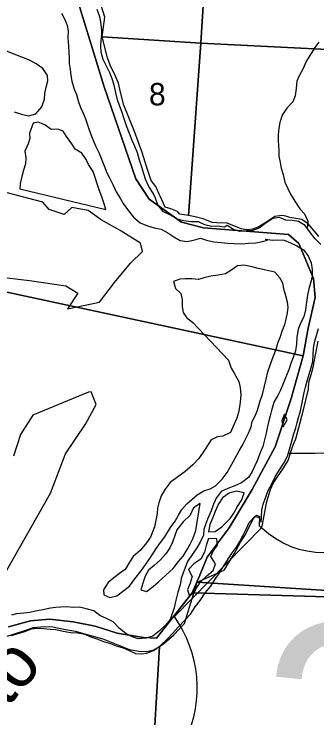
# Model space of a CAD drawing. Extents: x 114604 to 551442, y 316898 to 567001.
# Drawn here: x 203011 to 206000, y 360166 to 367116 of the extents above; entities that cross this region are included whole.
import ezdxf

# ---------------------------------------------------------------- set-up
doc = ezdxf.new("R2010")
doc.units = 0
for name, color, linetype in [('DV_X_County_Line', 7, 'Continuous'), ('GE_P_Alignment_500_Cardinal_Points', 7, 'Continuous'), ('GE_P_Alignment_500_Distances', 7, 'Continuous'), ('MT_X_Edge_Line', 7, 'Continuous'), ('PM_P_Cells', 7, 'Continuous'), ('PV_X_Curb', 7, 'Continuous'), ('RD_P_GR_Rt', 7, 'Continuous'), ('SN_P_Signs', 7, 'Continuous')]:
    doc.layers.add(name, color=color, linetype=linetype)

msp = doc.modelspace()

# ---------------------------------------------------------------- linework, layer by layer
at = {"layer": 'DV_X_County_Line'}
for points in [[(203480.5, 367126.5), (203514.6, 367056.4), (203534.7, 367002.3), (203544.7, 366952.3), (203542.8, 366882.1), (203546.9, 366802), (203551, 366737.9), (203555.1, 366679.8), (203555.1, 366627.7), (203563.2, 366567.6), (203571.3, 366509.5), (203581.4, 366453.4), (203605.5, 366373.3), (203625.5, 366321.2), (203647.6, 366251.1), (203667.7, 366195), (203693.8, 366136.9), (203715.9, 366080.9), (203740, 366012.8), (203754, 365962.7), (203782.1, 365894.6), (203816.2, 365816.5), (203846.3, 365750.4), (203872.4, 365682.3), (203900.5, 365616.2), (203926.6, 365548.1), (203952.6, 365498.1), (203984.7, 365432), (204018.8, 365361.9), (204058.9, 365297.9), (204089, 365245.8), (204141.1, 365173.7), (204189.2, 365111.7), (204255.3, 365055.7), (204327.3, 365025.7), (204395.3, 365005.7), (204463.4, 364991.8), (204529.4, 364955.8), (204589.5, 364915.8), (204651.5, 364879.9), (204715.6, 364871.9), (204781.6, 364884), (204849.5, 364902.1), (204911.6, 364884.2), (204981.6, 364868.3), (205053.6, 364860.3), (205119.6, 364852.4), (205183.7, 364850.5), (205255.7, 364848.6)], [(204270.6, 365604.7), (204250.5, 365674.8), (204228.4, 365744.9), (204200.3, 365817), (204178.2, 365869.1), (204150.1, 365937.2), (204122, 366013.3), (204095.9, 366091.4), (204077.8, 366143.5), (204051.8, 366213.5), (204031.7, 366269.6), (204015.6, 366337.7), (204001.5, 366401.8), (203983.4, 366465.9), (203959.3, 366530), (203923.2, 366602.1), (203889.1, 366668.2), (203871.1, 366740.3), (203867, 366804.4), (203870.9, 366854.5), (203876.8, 366904.6), (203876.8, 366956.7), (203868.7, 367038.8), (203856.6, 367088.9), (203830.5, 367161)], [(205089.4, 365010.7), (205017.4, 365020.6), (204963.4, 365018.5), (204895.4, 365036.5), (204831.3, 365064.4), (204759.3, 365064.3), (204687.3, 365074.3), (204619.3, 365092.2), (204555.2, 365130.2), (204485.2, 365164.2), (204431.1, 365232.2), (204407, 365298.3), (204382.9, 365348.4), (204340.8, 365412.4), (204308.7, 365484.5), (204290.6, 365538.6), (204270.6, 365604.7)], [(206039.8, 364841.6), (205981.7, 364897.6), (205925.6, 364969.7), (205883.6, 365029.7), (205819.5, 365067.7), (205757.5, 365077.7), (205693.5, 365081.6), (205631.4, 365107.6), (205565.4, 365097.4), (205499.5, 365053.3), (205431.5, 365003.1), (205363.5, 364979), (205311.5, 364974.9), (205239.5, 364968.8), (205175.5, 364988.7), (205115.4, 365028.7), (205089.4, 365010.7)], [(205511.7, 364883), (205493.7, 364895), (205561.7, 364885), (205611.7, 364887.1), (205677.7, 364885.2), (205739.7, 364857.2), (205801.8, 364827.3), (205867.9, 364787.3), (205913.9, 364729.2), (205944, 364661.1), (205952.1, 364595), (205954.2, 364522.9), (205940.3, 364472.8), (205920.4, 364404.6), (205906.4, 364340.5), (205896.5, 364272.3), (205888.6, 364196.2), (205870.7, 364126), (205838.8, 364063.9), (205814.8, 364001.7), (205802.9, 363925.6), (205799, 363857.5), (205789.1, 363791.3), (205767.2, 363725.2), (205743.3, 363665), (205723.3, 363602.9), (205697.4, 363540.7), (205671.5, 363474.6), (205639.6, 363402.4), (205613.6, 363350.3), (205579.7, 363290.1), (205555.8, 363215.9), (205537.9, 363149.8), (205525.9, 363099.7), (205510, 363031.5), (205500.1, 362977.4), (205482.2, 362913.3), (205466.2, 362845.1), (205444.3, 362793), (205410.4, 362704.8), (205362.5, 362600.6), (205324.6, 362538.4), (205256.7, 362488.2), (205188.7, 362458.1), (205120.7, 362429.9), (205054.7, 362401.8), (205006.8, 362335.6), (204978.9, 362275.4), (204955, 362209.3), (204921.1, 362129.1), (204899.1, 362075), (204885.2, 362024.9), (204879.2, 361970.8), (204847.3, 361902.6), (204813.4, 361846.4), (204771.5, 361782.3), (204723.6, 361712.1), (204699.6, 361651.9), (204679.7, 361597.8), (204661.8, 361541.7), (204649.8, 361481.5), (204625.9, 361407.4), (204608, 361327.2), (204590.1, 361253), (204550.3, 361136.8), (204510.3, 361084.6), (204446.4, 361024.4), (204380.4, 360974.3), (204312.4, 360954.1), (204236.4, 360948), (204176.4, 360966), (204114.4, 360998), (204050.3, 361048), (203988.2, 361116), (203924.1, 361148), (203858.1, 361176), (203798, 361222), (203724, 361241.9), (203658, 361259.8), (203595.9, 361257.8), (203527.9, 361263.7), (203471.9, 361259.6), (203421.9, 361257.5), (203369.9, 361249.5), (203293.9, 361233.3), (203223.9, 361221.2), (203167.9, 361207.1), (203105.9, 361199), (203033.9, 361192.9), (202983.9, 361180.8)], [(205255.7, 364848.6), (205323.7, 364852.7), (205395.7, 364858.8), (205461.7, 364870.9), (205511.7, 364883)], [(203184.1, 361044.8), (203236.1, 361050.9), (203300.2, 361049), (203368.2, 361043.1), (203422.2, 361039.1), (203496.2, 361023.2), (203568.2, 361009.3), (203640.3, 361005.4), (203708.3, 360991.4), (203760.3, 360971.4), (203826.4, 360945.5), (203894.4, 360921.5), (203962.4, 360901.6), (204018.5, 360877.6), (204088.5, 360857.7), (204140.6, 360833.7), (204208.6, 360801.7), (204272.6, 360799.8), (204322.6, 360805.9), (204386.6, 360832), (204454.6, 360876.2), (204522.5, 360944.4), (204578.4, 361002.6), (204630.4, 361062.8), (204698.3, 361133), (204752.2, 361189.1), (204800.1, 361261.3), (204848.1, 361325.5), (204896, 361399.7), (204951.9, 361465.9), (204995.8, 361536.1), (205031.8, 361590.3), (205065.7, 361642.4), (205111.6, 361712.6), (205157.5, 361784.8), (205207.5, 361853), (205239.4, 361907.1), (205273.3, 361969.3), (205305.2, 362035.4), (205331.2, 362095.6), (205389.1, 362155.8), (205426.3, 362146.8), (205449.2, 362099.7), (205453.1, 362151.8), (205457, 362220), (205471, 362276.1), (205500.9, 362354.3), (205514.8, 362404.4), (205554.7, 362476.6), (205588.6, 362546.7), (205632.6, 362616.9), (205674.5, 362683.1), (205710.4, 362751.3), (205726.3, 362805.4), (205746.3, 362875.6), (205770.2, 362961.8), (205792.1, 363031.9), (205806, 363082), (205819.9, 363132.1), (205835.9, 363186.3), (205851.8, 363260.4), (205865.7, 363328.6), (205873.6, 363380.7), (205887.6, 363430.8), (205901.5, 363482.9), (205925.4, 363561.1), (205943.3, 363625.2), (205959.3, 363685.3), (205963.2, 363755.5), (205967.1, 363817.6), (205979, 363887.7), (205995, 363941.9), (206014.9, 364010)], [(205681.9, 363164), (205654, 363099.9), (205668, 363041.8)], [(205668, 363041.8), (205705.9, 363110), (205681.9, 363164)], [(205282.8, 362390.1), (205202.8, 362404), (205132.8, 362385.9), (205066.8, 362339.7), (205024.9, 362273.5), (204995, 362205.3), (204973.1, 362145.2), (204943.1, 362077), (204929.2, 362004.9), (204995.2, 362007), (205063.2, 362053.2)], [(205063.2, 362053.2), (205145.1, 362135.4), (205179, 362187.6), (205214.9, 362253.7), (205258.9, 362319.9), (205282.8, 362390.1)], [(204929.3, 361936.8), (204907.4, 361868.6), (204889.5, 361802.5), (204855.5, 361734.3), (204785.6, 361686.1), (204733.7, 361629.9), (204767.7, 361563.9), (204749.8, 361495.7), (204723.9, 361435.6), (204742, 361365.5), (204795.9, 361413.6)], [(204795.9, 361413.6), (204803.9, 361435.7), (204851.8, 361509.9), (204913.8, 361568.1), (204977.7, 361622.2), (204999.6, 361686.4), (204951.5, 361758.5), (204977.5, 361812.6), (205019.4, 361870.8), (205013.3, 361932.9), (204929.3, 361936.8)], [(202984.2, 360980.4), (203116.2, 361020.7), (203184.1, 361044.8)]]:
    msp.add_lwpolyline(points, dxfattribs=at)
at = {"layer": 'GE_P_Alignment_500_Cardinal_Points'}
msp.add_line((205456.8, 362044.6), (204592.9, 361168.1), dxfattribs=at)
for centre, radius, start, end in [((206061.4, 362670.4), 870.2, 225.98646, 314.84047), ((203600.1, 360462.2), 1218.2, 334.96058, 35.41439)]:
    msp.add_arc(centre, radius, start, end, dxfattribs=at)
at = {"layer": 'GE_P_Alignment_500_Distances'}
for points in [[(203590.6, 367408.2), (203901.4, 366398.8), (204211.4, 365490.7), (204343, 365289.3), (204662.6, 365060.4), (204879.8, 365004.1), (205718.5, 364938), (205820.3, 364852), (205967.3, 364506.2), (205983.1, 364318.5), (205913.1, 364014.5), (205863.2, 363742), (199063.9, 365202.5)], [(207096.8, 361332.5), (204769.8, 361400.5), (204843.8, 361576.7), (204917.8, 361752.8), (205132.5, 362043.4), (205361, 362420.8), (205589.1, 362841.6), (205744.7, 363319.6), (205863.2, 363742), (205913.1, 364014.5), (205983.1, 364318.5), (205967.3, 364506.2), (205820.3, 364852), (205718.5, 364938), (204879.8, 365004.1), (204662.6, 365060.4), (204343, 365289.3), (204211.4, 365490.7), (203901.4, 366398.8), (203590.6, 367408.2)], [(199063.9, 365202.5), (205863.2, 363742), (205744.7, 363319.6), (205589.1, 362841.6), (205361, 362420.8), (205132.5, 362043.4), (204917.8, 361752.8), (204843.8, 361576.7), (204769.8, 361400.5), (204417.7, 360954.4), (204287.6, 360960.6), (204027.1, 361002.1), (203809.8, 361072.8), (203592.8, 361114.6), (203361.3, 361141.8), (203173.6, 361126), (202957.2, 361066.6)], [(202957.2, 361066.6), (203173.6, 361126), (203361.3, 361141.8), (203592.8, 361114.6), (203809.8, 361072.8), (204027.1, 361002.1), (204287.6, 360960.6), (204417.7, 360954.4), (204769.8, 361400.5), (207096.8, 361332.5), (208169.7, 361284.4), (208552.9, 361258.6), (209132.9, 361224.3), (209780.2, 361190.3), (210185.5, 361167.7), (211235.9, 361101.5), (211937.1, 361053.8), (213234, 360978.2), (213279.3, 360976.1), (214060.3, 360930.7), (215135.5, 360867.9), (217822.6, 360710.4), (220462.2, 360550.5), (222533.6, 360426.9)]]:
    msp.add_lwpolyline(points, dxfattribs=at)
at = {"layer": 'MT_X_Edge_Line'}
msp.add_line((203771.3, 363385.4), (203745.2, 363383.3), dxfattribs=at)
for points in [[(203161.7, 366660), (202175.7, 367047.1)], [(203010.4, 366149.8), (203084.3, 366127.3), (203154.2, 366112.9), (203226.4, 366132.5), (203284.8, 366200.2), (203311.3, 366276.2), (203315.7, 366332.3), (203328.1, 366394.4), (203342.5, 366458.4), (203340.8, 366510.6), (203293.2, 366579), (203227.5, 366623.5), (203161.7, 366660)], [(203916.7, 365186), (203901, 365242.2), (203877.4, 365312.5), (203851.9, 365380.8), (203793, 365561.6), (203745.4, 365630.1), (203721.7, 365680.3), (203678.1, 365742.7), (203612.3, 365783.2), (203580.6, 365833.5), (203527.1, 365908), (203495.4, 365958.4), (203441.5, 365980.7), (203375.4, 365975.2), (203313.7, 366023.7), (203249.8, 366048.1), (203199.7, 366038.4), (203163.1, 365940.4), (203164.8, 365886.3), (203150.4, 365834.3), (203117.9, 365762.3), (203125.5, 365698.1), (203125.1, 365636), (203102.7, 365574), (203086.3, 365512), (203071.9, 365443.9), (203067.5, 365391.8)], [(204257.6, 364852.4), (204057, 364980.1), (203870.6, 365085.8), (203742.2, 365175.5), (203581.9, 365207.1), (203505.9, 365136.7), (203357.6, 365186.3), (203295.4, 365260.3), (202551.8, 365454.4)], [(203067.5, 365391.8), (203916.7, 365186)], [(204279.8, 364772.3), (204257.6, 364852.4)], [(202885.9, 364519.2), (203162.4, 364484), (203523.1, 364433.1), (203641.4, 364359.3), (203537.5, 364206.6), (203853.9, 364271.8), (204003.8, 364466.7), (204159.8, 364657.7), (204279.8, 364772.3)], [(205127.8, 363697), (205153.3, 363620.7), (205185, 363570.4), (205228.5, 363487.9), (205244.1, 363427.7), (205249.7, 363355.5), (205243.2, 363283.4), (205228.6, 363195.3), (205208.2, 363127.3), (205179.7, 363059.3), (205147.2, 362983.3), (205071, 362947.7), (205018.9, 362942), (204956.7, 362912.4), (204896.1, 362818.6), (204833.4, 362728.8), (204775, 362665), (204696.5, 362595.3), (204626.2, 362545.6), (204551.8, 362490), (204503.3, 362424.2), (204462.9, 362360.3), (204438.4, 362288.3), (204428.1, 362236.2), (204421.8, 362186.1), (204396.9, 362054), (204356.3, 361950), (204317.9, 361896.2), (204255.4, 361820.4), (204187, 361760.7), (204148.6, 361702.8), (204106.1, 361630.9), (204051.8, 361591.2), (203995.5, 361549.4), (203939.2, 361503.7), (203894.7, 361431.8), (203898.4, 361381.7), (203956.2, 361355.2), (204024.4, 361372.8), (204094.8, 361422.5), (204151.1, 361466.2), (204201.5, 361538.1), (204266.1, 361617.9), (204312.5, 361683.7), (204359, 361751.6), (204411.5, 361833.4), (204447.9, 361885.3), (204500.3, 361953.1), (204555, 362045), (204601.4, 362108.8), (204633.8, 362168.8), (204668.1, 362224.7), (204716.5, 362280.5), (204766.8, 362322.3), (204817.1, 362368.1), (204883.4, 362409.7), (204947.6, 362427.4), (204997.8, 362459.1), (205064.3, 362524.8), (205114.7, 362588.7), (205143.1, 362642.6), (205193.7, 362732.5), (205234.1, 362802.4), (205264.5, 362858.3), (205290.8, 362910.3), (205325.3, 362976.2), (205349.7, 363040.2), (205362, 363094.2), (205394.4, 363154.1), (205414.8, 363206.1), (205441.4, 363296.2), (205461.8, 363358.2), (205480.2, 363430.2), (205500.8, 363512.3), (205517.3, 363584.3), (205541.8, 363660.3), (205568.2, 363732.3), (205596.7, 363808.3), (205619.2, 363876.3), (205641.5, 363932.3), (205657.9, 363984.3), (205682.3, 364052.3), (205696.7, 364104.4), (205711, 364164.4), (205717.4, 364220.5), (205709.7, 364270.6), (205694.1, 364332.9), (205678.5, 364389.1), (205662.9, 364457.3), (205635.2, 364511.6), (205583.6, 364568.1), (205497.6, 364588.7), (205421.7, 364603.2), (205361.8, 364619.6), (205279.8, 364636.2), (205217.8, 364628.5), (205149.4, 364582.9), (205099.2, 364551.1), (205027.1, 364537.5), (204953, 364528), (204884.9, 364512.4)], [(204884.9, 364512.4), (204830.7, 364496.7), (204764.7, 364503.1), (204700.7, 364501.5), (204646.6, 364497.8), (204584.5, 364474.2), (204604, 364405.9), (204655.7, 364355.5), (204669.3, 364293.3), (204670.9, 364225.1), (204680.6, 364170.9), (204712.3, 364120.6), (204771.5, 364073.2)], [(204884.9, 364512.4), (204830.7, 364496.7), (204764.7, 364503.1), (204700.7, 364501.5), (204646.6, 364497.8), (204584.5, 364474.2), (204604, 364405.9), (204655.7, 364355.5), (204669.3, 364293.3), (204670.9, 364225.1), (204680.6, 364170.9), (204712.3, 364120.6), (204778, 364068.1)], [(204771.5, 364073.2), (205127.8, 363697)], [(204771.5, 364073.2), (205127.8, 363697)], [(202940.9, 361624.5), (203370.3, 362385.7), (203517.9, 362773.1), (203715.7, 363066.4), (203821.6, 363259.2), (203771.3, 363385.4)], [(203745.2, 363383.3), (203196.7, 363157), (203072.9, 362964.1), (203005.1, 362749.4)], [(204846.6, 362281.7), (204782.3, 362240), (204749.8, 362168), (204679.4, 362102.3), (204618.8, 362022.5), (204598.5, 361966.5), (204574, 361900.6), (204549.7, 361846.6), (204509.3, 361786.7), (204452.8, 361722.9), (204392.5, 361671.2), (204338.1, 361623.4), (204305.8, 361565.5), (204281.3, 361495.5), (204260.9, 361429.5), (204318.8, 361415.1), (204383.2, 361464.8), (204437.5, 361508.5), (204507.9, 361574.2), (204580.4, 361641.9), (204634.9, 361709.7), (204679.2, 361763.6), (204719.6, 361827.5), (204750, 361881.4), (204776.4, 361935.4), (204804.9, 362015.3)], [(204804.9, 362015.3), (204846.6, 362281.7)]]:
    msp.add_lwpolyline(points, dxfattribs=at)
at = {"layer": 'PM_P_Cells'}
for points in [[(206019.3, 366839.5), (205981.2, 366785.4), (205929, 366707.3), (205898.9, 366653.3), (205860.7, 366573.1), (205824.6, 366507.1), (205802.5, 366455), (205794.3, 366380.9), (205784.2, 366308.8), (205764, 366248.7), (205701.9, 366188.6), (205655.8, 366118.5), (205635.6, 366046.4), (205623.5, 365988.3), (205619.3, 365924.2), (205619.2, 365868.1), (205621.1, 365816), (205623, 365765.9), (205624.9, 365713.8), (205636.7, 365651.7), (205648.6, 365593.6), (205668.4, 365531.5), (205684.2, 365457.3), (205714.1, 365395.2), (205739.9, 365339.1), (205781.8, 365268.9), (205831.6, 365192.7), (205877.4, 365142.6), (205911.3, 365070.4), (205904.2, 365000.2)], [(206201.9, 362766.1), (206046, 362780.3), (205984, 362778.3), (205920, 362778.4), (205717.8, 362776.3)]]:
    msp.add_lwpolyline(points, dxfattribs=at)
at = {"layer": 'SN_P_Signs'}
for points in [[(205184.9, 372126.8), (204854.1, 366827.9), (203880, 366893), (203907.8, 367087), (203793.4, 367445)], [(206020.1, 364918.9), (205994.1, 364952.9), (205914, 365044.8), (205849.9, 365086.8), (205731.9, 365108.6), (205693.9, 365120.6), (205653.9, 365126.6), (205583.9, 365118.5), (205523.9, 365074.4), (205426, 365014.3), (205364, 364992.3), (205308, 364986.2), (205252, 364994.2), (205113.9, 365050), (205011.9, 365053.9), (204965.9, 365057.9), (204877.9, 365095.8), (204797.8, 365113.7), (204731.8, 365127.6), (204854.1, 366827.9), (210120.7, 366565.7)], [(209779.5, 361186.3), (204817.4, 361505.3), (205083.3, 361625.6), (205183.1, 361785.8), (205245.1, 361899.8), (205295, 361975.9), (205362.8, 362118), (205386.8, 362152), (205404.8, 362168), (205432.8, 362156.1), (205430.9, 362062), (205444.9, 362050), (205460.9, 362058.1), (205504.7, 362304.1), (205541.6, 362421), (205572.5, 362488.2), (205674.4, 362638.3), (205716.3, 362706.4), (205754.2, 362822.4), (205768.1, 362870.4), (205792.1, 362922.5), (205865.8, 363196.6), (205915.6, 363412.7), (205921.5, 363482.7), (205945.5, 363566.7), (205963.4, 363630.7), (205989.3, 363768.8), (206013.2, 363886.8)], [(202921.7, 360965.4), (203117.7, 361027.6), (203203.7, 361057.7), (203309.7, 361067.8), (203393.7, 361065.9), (203518, 361040.4), (203617.8, 361024.1), (203719.8, 360994.2), (203885.9, 360948.4), (204050, 360882.5), (204148, 360840.6), (204244, 360824.7), (204322, 360820.8), (204390, 360836.9), (204446, 360870.9), (204166.6, 356134.1), (200846.1, 356348.9)]]:
    msp.add_lwpolyline(points, dxfattribs=at)
for points in [[(210406.1, 371835), (210120.7, 366565.7), (204854.1, 366827.9), (205184.9, 372126.8)], [(204854.1, 366827.9), (204731.8, 365127.6), (204647.8, 365141.6), (204625.7, 365167.6), (204557.7, 365193.5), (204503.7, 365209.4), (204451.6, 365317.4), (204443.6, 365337.4), (204409.5, 365413.4), (204363.4, 365473.3), (204325.3, 365591.3), (204271.1, 365759.2), (204200.9, 365955.2), (204094.7, 366217.1), (204060.5, 366345.1), (204042.4, 366433.1), (204012.4, 366503.1), (203960.3, 366611), (203934.2, 366683), (203880, 366893)], [(204817.4, 361505.3), (209779.5, 361186.3), (209446.2, 355850.9), (204166.6, 356134.1), (204446, 360870.9), (204486, 360897), (204587.9, 360985.1), (204691.8, 361097.2)]]:
    msp.add_lwpolyline(points, close=True, dxfattribs=at)

# ---------------------------------------------------------------- texts
at = {"layer": 'GE_P_Alignment_500_Cardinal_Points'}
msp.add_text('23', height=2088.43, rotation=0.41347, dxfattribs=at).set_placement((205457, 358998.9))
at = {"layer": 'PV_X_Curb'}
msp.add_text('8', height=221, rotation=0.41345, dxfattribs=at).set_placement((204343.6, 366214))
at = {"layer": 'RD_P_GR_Rt'}
msp.add_text('Scioto', height=500, rotation=49.18358, dxfattribs=at).set_placement((202089, 359275.5))

doc.saveas('drawing.dxf')
